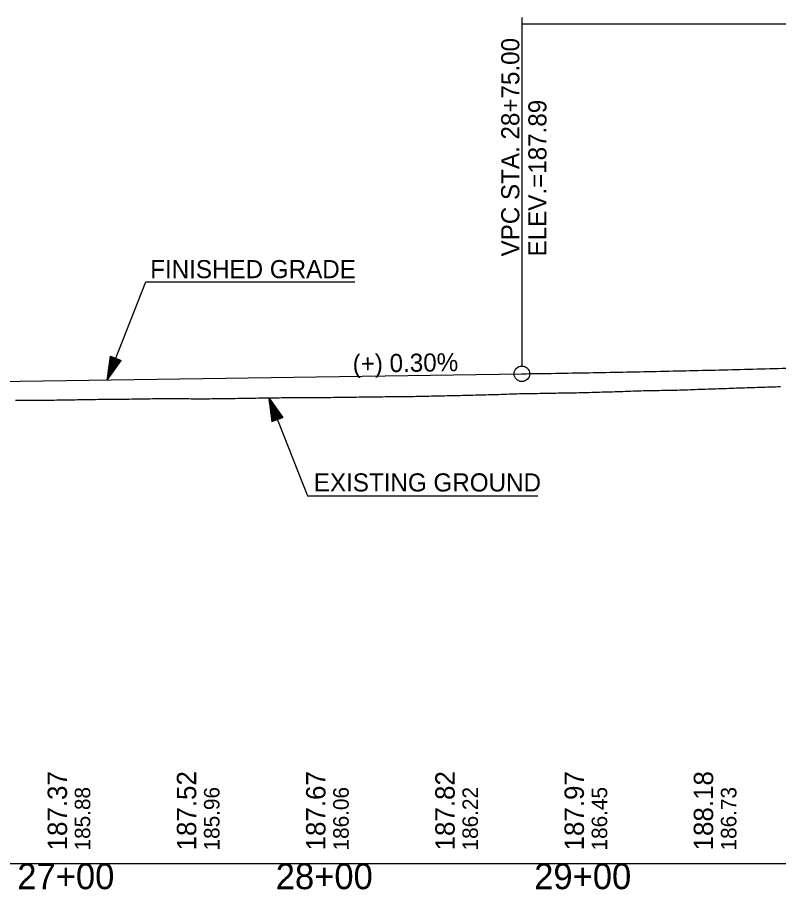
# Model space of a CAD drawing. Extents: x 69 to 2003113, y 512 to 837401.
# Drawn here: x 1890057.4 to 1890351.8, y 820540 to 820877.5 of the extents above; entities that cross this region are included whole.
import ezdxf

# ---------------------------------------------------------------- set-up
doc = ezdxf.new("R2010")
doc.units = 0
for name, color, linetype in [('BR_BORDER LINES', 7, 'Continuous'), ('BR_CENTER LINE BASELINE', 7, 'Continuous'), ('BR_CONCRETE', 7, 'Continuous'), ('BR_GRID DOTS', 7, 'Continuous'), ('BR_GRID LINES', 7, 'Continuous'), ('BR_TEXT', 7, 'Continuous'), ('RD_HC_Points', 7, 'Continuous'), ('RD_PD_ALT1_TrvlWay', 7, 'Continuous'), ('RD_SHT_ID', 7, 'Continuous')]:
    doc.layers.add(name, color=color, linetype=linetype)

msp = doc.modelspace()

# ---------------------------------------------------------------- linework, layer by layer
at = {"layer": 'BR_BORDER LINES'}
msp.add_line((1889077.53, 820550.13), (1895477.53, 820550.13), dxfattribs=at)
at = {"layer": 'BR_GRID DOTS'}
for p, q in [((1890252.53, 820877.48), (1890252.53, 820742.58)), ((1890252.53, 820874.98), (1890902.53, 820874.98))]:
    msp.add_line(p, q, dxfattribs=at)
msp.add_circle((1890252.53, 820739.58), 3, dxfattribs=at)
at = {"layer": 'BR_GRID LINES'}
msp.add_line((1889527.53, 820728.7), (1890252.53, 820739.58), dxfattribs=at)
msp.add_spline([(1890252.53, 820739.58), (1890265.53, 820739.78), (1890278.53, 820740.01), (1890291.53, 820740.26), (1890304.53, 820740.52), (1890317.53, 820740.81), (1890330.53, 820741.12), (1890343.53, 820741.45), (1890356.53, 820741.79), (1890369.53, 820742.16), (1890382.53, 820742.55), (1890395.53, 820742.96), (1890408.53, 820743.4), (1890421.53, 820743.85), (1890434.53, 820744.32), (1890447.53, 820744.81), (1890460.53, 820745.32), (1890473.53, 820745.86), (1890486.53, 820746.41), (1890499.53, 820746.99), (1890512.53, 820747.58), (1890525.53, 820748.2), (1890538.53, 820748.83), (1890551.53, 820749.49), (1890564.53, 820750.17), (1890577.53, 820750.87), (1890590.53, 820751.58), (1890603.53, 820752.32), (1890616.53, 820753.08), (1890629.53, 820753.86), (1890642.53, 820754.66), (1890655.53, 820755.48), (1890668.53, 820756.32), (1890681.53, 820757.19), (1890694.53, 820758.07), (1890707.53, 820758.97), (1890720.53, 820759.9), (1890733.53, 820760.84), (1890746.53, 820761.8), (1890759.53, 820762.79), (1890772.53, 820763.8), (1890785.53, 820764.82), (1890798.53, 820765.87), (1890811.53, 820766.93), (1890824.53, 820768.02), (1890837.53, 820769.13), (1890850.53, 820770.26), (1890863.53, 820771.41), (1890876.53, 820772.58), (1890889.53, 820773.77), (1890902.53, 820774.98)], degree=3, dxfattribs=at)
at = {"layer": 'BR_TEXT'}
for points in [[(1890204.6, 820730.78), (1890205.6, 820730.8), (1890206.6, 820730.81), (1890207.6, 820730.82), (1890208.6, 820730.83), (1890209.6, 820730.84), (1890210.6, 820730.85), (1890211.6, 820730.87), (1890212.6, 820730.89), (1890213.6, 820730.91), (1890214.6, 820730.93), (1890215.6, 820730.95), (1890216.6, 820730.98), (1890217.6, 820731), (1890218.6, 820731.02), (1890219.6, 820731.04), (1890220.6, 820731.07), (1890221.6, 820731.09), (1890222.6, 820731.11), (1890223.6, 820731.13), (1890224.6, 820731.15), (1890225.6, 820731.18), (1890226.6, 820731.2), (1890227.6, 820731.22), (1890228.6, 820731.24), (1890229.6, 820731.27), (1890230.6, 820731.29), (1890231.6, 820731.31), (1890232.6, 820731.34), (1890233.6, 820731.36), (1890234.6, 820731.38), (1890235.6, 820731.4), (1890236.6, 820731.43), (1890237.6, 820731.45), (1890238.6, 820731.47), (1890239.6, 820731.5), (1890240.6, 820731.52), (1890241.6, 820731.56), (1890242.6, 820731.59), (1890243.6, 820731.62), (1890244.6, 820731.66), (1890245.6, 820731.69), (1890246.6, 820731.72), (1890247.6, 820731.76), (1890248.6, 820731.79), (1890249.6, 820731.83), (1890250.6, 820731.86), (1890251.6, 820731.89), (1890252.6, 820731.91), (1890253.6, 820731.93), (1890254.6, 820731.95), (1890255.6, 820731.96), (1890256.6, 820731.98), (1890257.6, 820732), (1890258.6, 820732.01), (1890259.6, 820732.03), (1890260.6, 820732.05), (1890261.6, 820732.07), (1890262.6, 820732.08), (1890263.6, 820732.1), (1890264.6, 820732.12), (1890265.6, 820732.13), (1890266.6, 820732.15), (1890267.6, 820732.16), (1890268.6, 820732.18), (1890269.6, 820732.2), (1890270.6, 820732.21), (1890271.6, 820732.23), (1890272.6, 820732.24), (1890273.6, 820732.26), (1890274.6, 820732.28), (1890275.6, 820732.31), (1890276.6, 820732.34), (1890277.6, 820732.37), (1890278.6, 820732.4), (1890279.6, 820732.43), (1890280.6, 820732.46), (1890281.6, 820732.49), (1890282.6, 820732.53), (1890283.6, 820732.56), (1890284.6, 820732.59), (1890285.6, 820732.62), (1890286.6, 820732.63), (1890287.6, 820732.65), (1890288.6, 820732.68), (1890289.6, 820732.72), (1890290.6, 820732.75), (1890291.6, 820732.78), (1890292.6, 820732.82), (1890293.6, 820732.85), (1890294.6, 820732.88), (1890295.6, 820732.92), (1890296.6, 820732.95), (1890297.6, 820732.98), (1890298.6, 820733.02), (1890299.6, 820733.05), (1890300.6, 820733.08), (1890301.6, 820733.1), (1890302.6, 820733.12), (1890303.6, 820733.13), (1890304.6, 820733.15)], [(1890304.6, 820733.15), (1890305.6, 820733.17), (1890306.6, 820733.19), (1890307.6, 820733.2), (1890308.6, 820733.22), (1890309.6, 820733.24), (1890310.6, 820733.26), (1890311.6, 820733.28), (1890312.6, 820733.3), (1890313.6, 820733.33), (1890314.6, 820733.36), (1890315.6, 820733.4), (1890316.6, 820733.43), (1890317.6, 820733.47), (1890318.6, 820733.5), (1890319.6, 820733.54), (1890320.6, 820733.58), (1890321.6, 820733.61), (1890322.6, 820733.65), (1890323.6, 820733.68), (1890324.6, 820733.72), (1890325.6, 820733.74), (1890326.6, 820733.76), (1890327.6, 820733.79), (1890328.6, 820733.83), (1890329.6, 820733.86), (1890330.6, 820733.9), (1890331.6, 820733.94), (1890332.6, 820733.97), (1890333.6, 820734.01), (1890334.6, 820734.05), (1890335.6, 820734.09), (1890336.6, 820734.12), (1890337.6, 820734.16), (1890338.6, 820734.2), (1890339.6, 820734.23), (1890340.6, 820734.27), (1890341.6, 820734.3), (1890342.6, 820734.33), (1890343.6, 820734.36), (1890344.6, 820734.39), (1890345.6, 820734.43), (1890346.6, 820734.46), (1890347.6, 820734.49), (1890348.6, 820734.52), (1890349.6, 820734.55), (1890350.6, 820734.59), (1890351.6, 820734.63), (1890352.6, 820734.67)], [(1890056.6, 820729.34), (1890057.6, 820729.34), (1890058.6, 820729.34), (1890059.6, 820729.34), (1890060.6, 820729.34), (1890061.6, 820729.34), (1890062.6, 820729.35), (1890063.6, 820729.35), (1890064.6, 820729.35), (1890065.6, 820729.35), (1890066.6, 820729.36), (1890067.6, 820729.37), (1890068.6, 820729.38), (1890069.6, 820729.4), (1890070.6, 820729.41), (1890071.6, 820729.42), (1890072.6, 820729.44), (1890073.6, 820729.45), (1890074.6, 820729.46), (1890075.6, 820729.48), (1890076.6, 820729.49), (1890077.6, 820729.51), (1890078.6, 820729.54), (1890079.6, 820729.56), (1890080.6, 820729.58), (1890081.6, 820729.6), (1890082.6, 820729.62), (1890083.6, 820729.64), (1890084.6, 820729.65), (1890085.6, 820729.66), (1890086.6, 820729.67), (1890087.6, 820729.69), (1890088.6, 820729.7), (1890089.6, 820729.71), (1890090.6, 820729.72), (1890091.6, 820729.73), (1890092.6, 820729.74), (1890093.6, 820729.76), (1890094.6, 820729.77), (1890095.6, 820729.78), (1890096.6, 820729.78), (1890097.6, 820729.79), (1890098.6, 820729.79), (1890099.6, 820729.79), (1890100.6, 820729.81), (1890101.6, 820729.83), (1890102.6, 820729.84), (1890103.6, 820729.86), (1890104.6, 820729.88)], [(1890104.6, 820729.88), (1890105.6, 820729.89), (1890106.6, 820729.91), (1890107.6, 820729.93), (1890108.6, 820729.94), (1890109.6, 820729.96), (1890110.6, 820729.97), (1890111.6, 820729.99), (1890112.6, 820730.01), (1890113.6, 820730.01), (1890114.6, 820730.01), (1890115.6, 820730.01), (1890116.6, 820730.01), (1890117.6, 820730), (1890118.6, 820729.99), (1890119.6, 820729.99), (1890120.6, 820729.98), (1890121.6, 820729.97), (1890122.6, 820729.97), (1890123.6, 820729.96), (1890124.6, 820729.95), (1890125.6, 820729.95), (1890126.6, 820729.94), (1890127.6, 820729.94), (1890128.6, 820729.93), (1890129.6, 820729.93), (1890130.6, 820729.94), (1890131.6, 820729.95), (1890132.6, 820729.97), (1890133.6, 820729.98), (1890134.6, 820729.99), (1890135.6, 820730), (1890136.6, 820730.02), (1890137.6, 820730.03), (1890138.6, 820730.04), (1890139.6, 820730.06), (1890140.6, 820730.07), (1890141.6, 820730.08), (1890142.6, 820730.1), (1890143.6, 820730.11), (1890144.6, 820730.12), (1890145.6, 820730.13), (1890146.6, 820730.15), (1890147.6, 820730.16), (1890148.6, 820730.18), (1890149.6, 820730.19), (1890150.6, 820730.21), (1890151.6, 820730.22), (1890152.6, 820730.24), (1890153.6, 820730.25), (1890154.6, 820730.27), (1890155.6, 820730.28), (1890156.6, 820730.3), (1890157.6, 820730.31), (1890158.6, 820730.33), (1890159.6, 820730.34), (1890160.6, 820730.36), (1890161.6, 820730.36), (1890162.6, 820730.37), (1890163.6, 820730.37), (1890164.6, 820730.38), (1890165.6, 820730.38), (1890166.6, 820730.39), (1890167.6, 820730.39), (1890168.6, 820730.4), (1890169.6, 820730.4), (1890170.6, 820730.41), (1890171.6, 820730.41), (1890172.6, 820730.42), (1890173.6, 820730.42), (1890174.6, 820730.43), (1890175.6, 820730.43), (1890176.6, 820730.44), (1890177.6, 820730.45), (1890178.6, 820730.46), (1890179.6, 820730.48), (1890180.6, 820730.49), (1890181.6, 820730.5), (1890182.6, 820730.51), (1890183.6, 820730.53), (1890184.6, 820730.54), (1890185.6, 820730.55), (1890186.6, 820730.57), (1890187.6, 820730.58), (1890188.6, 820730.59), (1890189.6, 820730.6), (1890190.6, 820730.62), (1890191.6, 820730.63), (1890192.6, 820730.64), (1890193.6, 820730.66), (1890194.6, 820730.67), (1890195.6, 820730.68), (1890196.6, 820730.69), (1890197.6, 820730.7), (1890198.6, 820730.72), (1890199.6, 820730.73), (1890200.6, 820730.74), (1890201.6, 820730.75), (1890202.6, 820730.76), (1890203.6, 820730.77), (1890204.6, 820730.78)]]:
    msp.add_lwpolyline(points, dxfattribs=at)
at = {"layer": 'RD_PD_ALT1_TrvlWay'}
for p, q in [((1890092.11, 820737.16), (1890107.07, 820775.12)), ((1890107.07, 820775.12), (1890187.85, 820775.12)), ((1890092.11, 820737.16), (1890093.31, 820746.36)), ((1890092.11, 820737.16), (1890093.31, 820746.36)), ((1890095.41, 820745.53), (1890092.11, 820737.16)), ((1890095.41, 820745.53), (1890092.11, 820737.16)), ((1890092.11, 820737.16), (1890097.5, 820744.71)), ((1890092.11, 820737.16), (1890097.5, 820744.71)), ((1890093.31, 820746.36), (1890097.5, 820744.71)), ((1890093.31, 820746.36), (1890097.5, 820744.71)), ((1890154.6, 820730.27), (1890169.56, 820692.31)), ((1890157.9, 820721.9), (1890154.6, 820730.27)), ((1890154.6, 820730.27), (1890160, 820722.72)), ((1890154.6, 820730.27), (1890155.81, 820721.07)), ((1890155.81, 820721.07), (1890160, 820722.72)), ((1890169.56, 820692.31), (1890258.75, 820692.31))]:
    msp.add_line(p, q, dxfattribs=at)
for points in [[(1890095.31, 820745.45), (1890092.23, 820737.66), (1890095.27, 820745.53), (1890092.31, 820738.05), (1890095.17, 820745.53), (1890092.33, 820738.32), (1890095.06, 820745.55), (1890092.36, 820738.65), (1890094.98, 820745.6), (1890092.44, 820739.14), (1890094.87, 820745.67), (1890092.52, 820739.67), (1890094.75, 820745.67), (1890092.58, 820740.06), (1890094.67, 820745.72), (1890092.64, 820740.52), (1890094.56, 820745.71), (1890092.7, 820740.92), (1890094.51, 820745.81), (1890092.73, 820741.26), (1890094.37, 820745.82), (1890092.79, 820741.76), (1890094.27, 820745.88), (1890092.9, 820742.36), (1890094.18, 820745.94), (1890092.91, 820742.78), (1890094.07, 820745.98), (1890093, 820743.4), (1890093.95, 820745.99), (1890093.09, 820743.9), (1890093.85, 820746.09), (1890093.15, 820744.34), (1890093.75, 820746.09), (1890093.19, 820744.75), (1890093.67, 820746.18), (1890093.26, 820745.24), (1890093.56, 820746.14), (1890093.34, 820745.79), (1890093.44, 820746.15)], [(1890095.31, 820745.45), (1890092.23, 820737.66), (1890095.27, 820745.53), (1890092.31, 820738.05), (1890095.17, 820745.53), (1890092.33, 820738.32), (1890095.06, 820745.55), (1890092.36, 820738.65), (1890094.98, 820745.6), (1890092.44, 820739.14), (1890094.87, 820745.67), (1890092.52, 820739.67), (1890094.75, 820745.67), (1890092.58, 820740.06), (1890094.67, 820745.72), (1890092.64, 820740.52), (1890094.56, 820745.71), (1890092.7, 820740.92), (1890094.51, 820745.81), (1890092.73, 820741.26), (1890094.37, 820745.82), (1890092.79, 820741.76), (1890094.27, 820745.88), (1890092.9, 820742.36), (1890094.18, 820745.94), (1890092.91, 820742.78), (1890094.07, 820745.98), (1890093, 820743.4), (1890093.95, 820745.99), (1890093.09, 820743.9), (1890093.85, 820746.09), (1890093.15, 820744.34), (1890093.75, 820746.09), (1890093.19, 820744.75), (1890093.67, 820746.18), (1890093.26, 820745.24), (1890093.56, 820746.14), (1890093.34, 820745.79), (1890093.44, 820746.15)], [(1890092.38, 820737.68), (1890095.43, 820745.41), (1890092.54, 820737.94), (1890095.53, 820745.37), (1890092.7, 820738.18), (1890095.61, 820745.37), (1890092.88, 820738.39), (1890095.68, 820745.33), (1890093.08, 820738.65), (1890095.77, 820745.31), (1890093.26, 820738.9), (1890095.84, 820745.28), (1890093.48, 820739.19), (1890095.93, 820745.27), (1890093.72, 820739.55), (1890096.05, 820745.2), (1890093.93, 820739.87), (1890096.13, 820745.21), (1890094.16, 820740.2), (1890096.21, 820745.16), (1890094.4, 820740.51), (1890096.3, 820745.12), (1890094.63, 820740.86), (1890096.35, 820745.04), (1890094.95, 820741.31), (1890096.45, 820745.05), (1890095.19, 820741.6), (1890096.53, 820745.05), (1890095.48, 820741.98), (1890096.6, 820744.98), (1890095.72, 820742.39), (1890096.7, 820744.93), (1890095.94, 820742.7), (1890096.78, 820744.83), (1890096.19, 820742.98), (1890096.85, 820744.81), (1890096.48, 820743.45), (1890097, 820744.83), (1890096.66, 820743.72), (1890097.14, 820744.77), (1890096.85, 820743.89), (1890097.24, 820744.63), (1890097.36, 820744.68), (1890097.21, 820744.64)], [(1890092.38, 820737.68), (1890095.43, 820745.41), (1890092.54, 820737.94), (1890095.53, 820745.37), (1890092.7, 820738.18), (1890095.61, 820745.37), (1890092.88, 820738.39), (1890095.68, 820745.33), (1890093.08, 820738.65), (1890095.77, 820745.31), (1890093.26, 820738.9), (1890095.84, 820745.28), (1890093.48, 820739.19), (1890095.93, 820745.27), (1890093.72, 820739.55), (1890096.05, 820745.2), (1890093.93, 820739.87), (1890096.13, 820745.21), (1890094.16, 820740.2), (1890096.21, 820745.16), (1890094.4, 820740.51), (1890096.3, 820745.12), (1890094.63, 820740.86), (1890096.35, 820745.04), (1890094.95, 820741.31), (1890096.45, 820745.05), (1890095.19, 820741.6), (1890096.53, 820745.05), (1890095.48, 820741.98), (1890096.6, 820744.98), (1890095.72, 820742.39), (1890096.7, 820744.93), (1890095.94, 820742.7), (1890096.78, 820744.83), (1890096.19, 820742.98), (1890096.85, 820744.81), (1890096.48, 820743.45), (1890097, 820744.83), (1890096.66, 820743.72), (1890097.14, 820744.77), (1890096.85, 820743.89), (1890097.24, 820744.63), (1890097.36, 820744.68), (1890097.21, 820744.64)], [(1890157.8, 820721.98), (1890154.73, 820729.77), (1890157.77, 820721.9), (1890154.8, 820729.38), (1890157.67, 820721.9), (1890154.83, 820729.11), (1890157.56, 820721.88), (1890154.86, 820728.78), (1890157.48, 820721.83), (1890154.93, 820728.29), (1890157.36, 820721.76), (1890155.02, 820727.76), (1890157.25, 820721.76), (1890155.07, 820727.37), (1890157.17, 820721.71), (1890155.13, 820726.91), (1890157.06, 820721.72), (1890155.19, 820726.51), (1890157, 820721.62), (1890155.23, 820726.16), (1890156.86, 820721.61), (1890155.28, 820725.67), (1890156.77, 820721.55), (1890155.4, 820725.07), (1890156.67, 820721.49), (1890155.4, 820724.65), (1890156.57, 820721.45), (1890155.49, 820724.03), (1890156.45, 820721.44), (1890155.59, 820723.52), (1890156.35, 820721.34), (1890155.64, 820723.09), (1890156.25, 820721.34), (1890155.68, 820722.68), (1890156.16, 820721.25), (1890155.75, 820722.19), (1890156.05, 820721.29), (1890155.83, 820721.64), (1890155.93, 820721.28)], [(1890154.88, 820729.75), (1890157.92, 820722.02), (1890155.04, 820729.49), (1890158.03, 820722.06), (1890155.19, 820729.25), (1890158.11, 820722.06), (1890155.37, 820729.04), (1890158.17, 820722.1), (1890155.58, 820728.78), (1890158.26, 820722.12), (1890155.76, 820728.53), (1890158.33, 820722.15), (1890155.97, 820728.24), (1890158.43, 820722.16), (1890156.22, 820727.88), (1890158.54, 820722.23), (1890156.42, 820727.56), (1890158.62, 820722.22), (1890156.65, 820727.23), (1890158.7, 820722.27), (1890156.89, 820726.92), (1890158.79, 820722.31), (1890157.13, 820726.57), (1890158.84, 820722.38), (1890157.45, 820726.12), (1890158.94, 820722.38), (1890157.68, 820725.83), (1890159.02, 820722.38), (1890157.97, 820725.45), (1890159.1, 820722.45), (1890158.21, 820725.04), (1890159.19, 820722.5), (1890158.44, 820724.73), (1890159.28, 820722.6), (1890158.69, 820724.45), (1890159.35, 820722.62), (1890158.97, 820723.98), (1890159.49, 820722.6), (1890159.16, 820723.71), (1890159.63, 820722.66), (1890159.34, 820723.54), (1890159.74, 820722.8), (1890159.86, 820722.75), (1890159.7, 820722.79)]]:
    msp.add_lwpolyline(points, dxfattribs=at)

# ---------------------------------------------------------------- texts
at = {"layer": 'BR_CENTER LINE BASELINE'}
msp.add_text('(+) 0.30%', height=7, rotation=0.8594, dxfattribs=at).set_placement((1890187.09, 820740))
at = {"layer": 'BR_CONCRETE'}
for s, height, p in [('VPC STA. 28+75.00 ', 7, (1890251.53, 820784.98)), ('ELEV.=187.89', 7, (1890262.03, 820784.98)), ('185.88', 6, (1890085.53, 820555.13)), ('185.96', 6, (1890135.53, 820555.13)), ('186.06', 6, (1890185.53, 820555.13)), ('186.22', 6, (1890235.53, 820555.13)), ('186.45', 6, (1890285.53, 820555.13)), ('186.73', 6, (1890335.53, 820555.13))]:
    msp.add_text(s, height=height, rotation=90, dxfattribs=at).set_placement(p)
at = {"layer": 'RD_HC_Points'}
for s, p in [('187.37', (1890076.53, 820555.13)), ('187.52', (1890126.53, 820555.13)), ('187.67', (1890176.53, 820555.13)), ('187.82', (1890226.53, 820555.13)), ('187.97', (1890276.53, 820555.13)), ('188.18', (1890326.53, 820555.13))]:
    msp.add_text(s, height=7.5, rotation=90, dxfattribs=at).set_placement(p)
at = {"layer": 'RD_PD_ALT1_TrvlWay'}
for s, p in [('FINISHED GRADE', (1890108.71, 820776.58)), ('EXISTING GROUND', (1890172.03, 820694.04))]:
    msp.add_text(s, height=7, dxfattribs=at).set_placement(p)
at = {"layer": 'RD_SHT_ID'}
for s, p in [('27+00', (1890057.29, 820540.13)), ('28+00', (1890157.29, 820540.13)), ('29+00', (1890257.29, 820540.13))]:
    msp.add_text(s, height=10, dxfattribs=at).set_placement(p)

doc.saveas('drawing.dxf')
